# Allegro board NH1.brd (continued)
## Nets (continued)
+V_IPSOUT: C1AP1.1 C1AP4.1 C1AP5.1 C1AP8.1 C1AP12.1 C1AP14.1 C1AP20.1 C1AP31.1 C1AP34.1 C1AP37.1 C1AP42.1 C415.2 R1AP1.2 R1AP6.1 R56.2 R57.2 RT1HDMI1.1 U1AP1.8 U1AP1.15 U1AP1.19 U1AP1.22 U1AP1.25 U1AP1.26 U1AP1.37 U1AP1.43 U1AP1.44 U1AP1.45 U1AP1.59 U1AP1.60 U1AP1.72 U1AP1.76 U28.2 U28.3
+V_VBUS: C1AP15.1 C1P1.1 C1P2.1 CR1AP1.3 CR1P1.2 J1P1.1 R1AP6.2 R1AP7.2 U1AP1.55 U1AP1.61
+V_VCC: C1AP2.1 C1AP3.1 C1AP43.1 C1AP44.1 C1AS93.1 C1AS95.1 C1AS97.1 L1AP1.1 TVS2.2 U1.A12 U1.F15 U1.G15 U1.H14 U1.H15 U1.H16 U1.J17 U1.K13 U1.K14 U1.K15 U1.K16 U1.L14 U1.L15 U1.L16 U1.M14 U1.M15 U1.N14 U1.N15 U1.P13 U1.P14 U1.P15 U1.P16 U1AP1.29
+V_VCC_LX: L1AP1.2 U1AP1.27 U1AP1.28
+V_VNN: C1AP10.1 C1AP11.1 C1AP45.1 C1AS94.1 C1AS96.1 L1AP5.2 L1AP6.2 TVS1.2 U1.AB1 U1.K12 U1.L9 U1.L11 U1.L12 U1.L13 U1.M8 U1.M9 U1.M10 U1.M11 U1.M12 U1.N10 U1.N11 U1.N12 U1.R8 U1.R13 U1.T11 U1.T12 U1.T13 U1.T14 U1.T15 U1.T16 U1.T17 U1.U10 U1.U11 U1.U12 U1.U13 U1.U14 U1.U15 U1.U16 U1.V10 U1.V11 U1.V13 U1.V17 U1.V18 U1.W18 U1AP1.46
+V_VNN_PH1_LX: L1AP5.1 U1AP1.41 U1AP1.42
+V_VNN_PH2_LX: L1AP6.1 U1AP1.47 U1AP1.48
+V_VTT: C1AM25.1 C1AP36.1 R1AM13.1 R1AM20.1 R1AM21.1 U1AP1.7
+VREFCAL: C1AM5.2 C1AM11.2 R1AM5.1 R1AM6.2 U1AM1.M8 U1AM2.M8
+VREFCAU: C1AM17.2 C1AM23.2 R1AM9.1 R1AM10.2 U1AM3.M8 U1AM4.M8
+VREFDQL: C1AM6.2 C1AM12.2 R1AM7.1 R1AM8.2 U1AM1.H1 U1AM2.H1
+VREFDQU: C1AM18.2 C1AM24.2 R1AM11.1 R1AM12.2 U1AM3.H1 U1AM4.H1
+VRTC: C1AP35.1 CR1RTC1.1 U1AP1.53
+VRTC_CH: C1RTC1.1 CR1RTC1.3 R1AS5.1 R1AS11.1 U1.F11
+VSDIO: C1AS116.1 C88.2 R1AP11.2 U1.W14 U15.15 U15.16
+VSDIO1: R1AP12.1 R1WF13.2
ALDO1: C1AP21.1 U1AP1.33
ALDO2: C1AP22.1 U1AP1.34
ALDO3: C1AP23.1 U1AP1.36
BRTCX1_PAD_B8: C1AS66.1 R1AS54.1 U1.D1 Y1.2
BRTCX2_PAD_C7: C1AS67.1 R1AS54.2 U1.E1 Y1.1
BT_DEV_EN: R1WF3.1 U1.E16 U1WF1.12
BT_DEV_WAKE: R1WF5.1 U1.E17 U1WF1.20
BT_HOST_WAKE: U1.D9 U1WF1.21
BVCCRTC_EXPAD: C1AS65.1 U1.D2
CEXT_ALS: C1HDMI11.2 EU1HDMI1.17
COREPWROK: TP25.1 U1.F2 U1AP1.50
DDI0_HDMI_CLK_DN: C1HDMI2.1 EU1HDMI1.10
DDI0_HDMI_CLK_DN_ALS: J1HDMI1.12 L1HDMI1.2 R1HDMI10.2
DDI0_HDMI_CLK_DN_CH: EU1HDMI1.18 L1HDMI1.1 R1HDMI10.1
DDI0_HDMI_CLK_DP: C1HDMI1.1 EU1HDMI1.9
DDI0_HDMI_CLK_DP_ALS: J1HDMI1.10 L1HDMI1.3 R1HDMI9.2
DDI0_HDMI_CLK_DP_CH: EU1HDMI1.19 L1HDMI1.4 R1HDMI9.1
DDI0_HDMI_D0_DN: C1HDMI4.1 EU1HDMI1.7
DDI0_HDMI_D0_DN_ALS: EU1HDMI1.21 J1HDMI1.9
DDI0_HDMI_D0_DP: C1HDMI3.1 EU1HDMI1.6
DDI0_HDMI_D0_DP_ALS: EU1HDMI1.22 J1HDMI1.7
DDI0_HDMI_D1_DN: C1HDMI6.1 EU1HDMI1.5
DDI0_HDMI_D1_DN_ALS: EU1HDMI1.23 J1HDMI1.6
DDI0_HDMI_D1_DP: C1HDMI5.1 EU1HDMI1.4
DDI0_HDMI_D1_DP_ALS: EU1HDMI1.24 J1HDMI1.4
DDI0_HDMI_D2_DN: C1HDMI8.1 EU1HDMI1.2
DDI0_HDMI_D2_DN_ALS: EU1HDMI1.26 J1HDMI1.3
DDI0_HDMI_D2_DP: C1HDMI7.1 EU1HDMI1.1
DDI0_HDMI_D2_DP_ALS: EU1HDMI1.27 J1HDMI1.1
DDI0_HDMI_HPD_ALS: EU1HDMI1.25 J1HDMI1.19
DDI0_HDMI_HPD_ESD: EU1HDMI1.3 Q1HDMI2.1 R1HDMI6.2
DDI0_HDMI_SCL: EU1HDMI1.31 R1HDMI4.1 U1.C13
DDI0_HDMI_SCL_ALS: EU1HDMI1.28 J1HDMI1.15 R57.1
DDI0_HDMI_SDA: EU1HDMI1.32 R1HDMI5.1 U1.D13
DDI0_HDMI_SDA_ALS: EU1HDMI1.29 J1HDMI1.16 R56.1
DDI0_HPD_N: Q1HDMI2.3 R1HDMI3.1 U1.E14
DDI0_PLLOBS_DN: R1AS26.1 U1.AA4
DDI0_PLLOBS_DP: R1AS26.2 U1.AA3
DDI0_TX0_DN: C1HDMI8.2 U1.AB3
DDI0_TX0_DP: C1HDMI7.2 U1.AB4
DDI0_TX1_DN: C1HDMI6.2 U1.AA1
DDI0_TX1_DP: C1HDMI5.2 U1.AB2
DDI0_TX2_DN: C1HDMI4.2 U1.Y1
DDI0_TX2_DP: C1HDMI3.2 U1.Y2
DDI0_TX3_DN: C1HDMI2.2 U1.Y3
DDI0_TX3_DP: C1HDMI1.2 U1.Y4
DDR3_DRAM_PWROK: R1AS12.2 U1.AC20 U1AP1.11
DDR3_SOC_CMDPU: R1AS64.2 U1.AE21
DDR3_SOC_DQTPU: R1AS73.2 U1.AE20
DDR3_SOC_ODTPU: R1AS63.2 U1.AE22
DDR3_VCCA_PWROK: R1AS36.2 U1.AB20 U1AP1.12
DDR3_VREF: C1AS71.2 R1AS76.2 R1AS77.1 U1.AD20
DDR3L_ZQ_L8_A: R1AM1.1 U1AM1.L8
DDR3L_ZQ_L8_B: R1AM2.1 U1AM2.L8
DDR3L_ZQ_L8_C: R1AM3.1 U1AM3.L8
DDR3L_ZQ_L8_D: R1AM4.1 U1AM4.L8
DLD01: C1AP24.1 U1AP1.21
DLDO4: C1AP27.1 U1AP1.17
ELDO2: C1AP29.1 U1AP1.2
EMMC_CLK: U1.AE8 U1EMMC1.M6
EMMC_CMD: U1.AB8 U1EMMC1.M5
EMMC_DATA_0: U1.AB7 U1EMMC1.A3
EMMC_DATA_1: U1.AC7 U1EMMC1.A4
EMMC_DATA_2: U1.AC8 U1EMMC1.A5
EMMC_DATA_3: U1.AB9 U1EMMC1.B2
EMMC_DATA_4: U1.AA9 U1EMMC1.B3
EMMC_DATA_5: U1.AA8 U1EMMC1.B4
EMMC_DATA_6: U1.Y8 U1EMMC1.B5
EMMC_DATA_7: U1.Y7 U1EMMC1.B6
EMMC_RESET: U1.AD8 U1EMMC1.K5
GPIO_RCOMP: R1AS49.1 U1.A4
HDA_RCOMP: R1AS45.1 U1.AE14
HDMI_POWER_DN: EU1HDMI1.12 R1HDMI1.2
HOLD_N_FLASH: EU1SPI1.7 R1SPI4.1
I2C_4_PMIC_SCL: R69.2 TP24.1 U1.AE16 U1AP1.51
I2C_4_PMIC_SDA: R68.2 TP23.1 U1.AD16 U1AP1.52
I2S_1_BT_WWAN_CLK: U1.AC13 U1WF1.16
I2S_1_BT_WWAN_FS: U1.AC14 U1WF1.17
I2S_1_BT_WWAN_RXD: U1.Y10 U1WF1.14
I2S_1_BT_WWAN_TXD: U1.AB14 U1WF1.15
ICLK_ICOMP: R1AS51.1 U1.V1
M0_BS0: U1.M21 U1AM1.M2 U1AM2.M2 U1AM3.M2 U1AM4.M2
M0_BS1: U1.N19 U1AM1.N8 U1AM2.N8 U1AM3.N8 U1AM4.N8
M0_BS2: U1.K22 U1AM1.M3 U1AM2.M3 U1AM3.M3 U1AM4.M3
M0_CASB: U1.P20 U1AM1.K3 U1AM2.K3 U1AM3.K3 U1AM4.K3
M0_CKE0: R1AM13.2 U1.G22 U1AM1.K9 U1AM2.K9 U1AM3.K9 U1AM4.K9
M0_CLK0_DN: R1AS55.1 U1.J22 U1AM1.K7 U1AM2.K7 U1AM3.K7 U1AM4.K7
M0_CLK0_DP: R1AS55.2 U1.J23 U1AM1.J7 U1AM2.J7 U1AM3.J7 U1AM4.J7
M0_CS0_B: R1AM20.2 U1.P22 U1AM1.L2 U1AM2.L2 U1AM3.L2 U1AM4.L2
M0_DATA0: U1.D18 U1AM2.C8
M0_DATA1: U1.B18 U1AM2.A7
M0_DATA2: U1.A21 U1AM2.A3
M0_DATA3: U1.C18 U1AM2.B8
M0_DATA4: U1.A22 U1AM2.C2
M0_DATA5: U1.B20 U1AM2.D7
M0_DATA6: U1.A18 U1AM2.A2
M0_DATA7: U1.B22 U1AM2.C3
M0_DATA8: U1.C20 U1AM2.H3
M0_DATA9: U1.D23 U1AM2.F7
M0_DATA10: U1.E19 U1AM2.F2
M0_DATA11: U1.E23 U1AM2.H8
M0_DATA12: U1.D22 U1AM2.H7
M0_DATA13: U1.E22 U1AM2.F8
M0_DATA14: U1.E20 U1AM2.G2
M0_DATA15: U1.D20 U1AM2.E3
M0_DATA16: U1.E25 U1AM1.A3
M0_DATA17: U1.A23 U1AM1.C8
M0_DATA18: U1.C23 U1AM1.A7
M0_DATA19: U1.F25 U1AM1.C2
M0_DATA20: U1.B24 U1AM1.D7
M0_DATA21: U1.D24 U1AM1.C3
M0_DATA22: U1.B23 U1AM1.B8
M0_DATA23: U1.F24 U1AM1.A2
M0_DATA24: U1.F20 U1AM1.H8
M0_DATA25: U1.F21 U1AM1.H7
M0_DATA26: U1.G20 U1AM1.F7
M0_DATA27: U1.H23 U1AM1.H3
M0_DATA28: U1.G21 U1AM1.F8
M0_DATA29: U1.J21 U1AM1.F2
M0_DATA30: U1.J20 U1AM1.G2
M0_DATA31: U1.H22 U1AM1.E3
M0_DATA32: U1.AD24 U1AM3.A3
M0_DATA33: U1.AB25 U1AM3.A7
M0_DATA34: U1.Y24 U1AM3.B8
M0_DATA35: U1.AE23 U1AM3.A2
M0_DATA36: U1.AA25 U1AM3.D7
M0_DATA37: U1.AC23 U1AM3.C3
M0_DATA38: U1.AD23 U1AM3.C2
M0_DATA39: U1.Y25 U1AM3.C8
M0_DATA40: U1.V23 U1AM4.D7
M0_DATA41: U1.T24 U1AM4.C3
M0_DATA42: U1.W22 U1AM4.C8
M0_DATA43: U1.W23 U1AM4.B8
M0_DATA44: U1.R23 U1AM4.A2
M0_DATA45: U1.R22 U1AM4.C2
M0_DATA46: U1.V22 U1AM4.A7
M0_DATA47: U1.T25 U1AM4.A3
M0_DATA48: U1.AB22 U1AM4.H7
M0_DATA49: U1.AC22 U1AM4.F8
M0_DATA50: U1.Y19 U1AM4.G2
M0_DATA51: U1.AD22 U1AM4.F7
M0_DATA52: U1.AA22 U1AM4.H8
M0_DATA53: U1.Y23 U1AM4.E3
M0_DATA54: U1.Y20 U1AM4.H3
M0_DATA55: U1.Y21 U1AM4.F2
M0_DATA56: U1.T22 U1AM3.F7
M0_DATA57: U1.T20 U1AM3.F8
M0_DATA58: U1.W20 U1AM3.F2
M0_DATA59: U1.V20 U1AM3.H8
M0_DATA60: U1.U21 U1AM3.H3
M0_DATA61: U1.W21 U1AM3.E3
M0_DATA62: U1.U20 U1AM3.G2
M0_DATA63: U1.T21 U1AM3.H7
M0_DM0: U1.A20 U1AM2.D3
M0_DM1: U1.D21 U1AM2.E7
M0_DM2: U1.D25 U1AM1.D3
M0_DM3: U1.F19 U1AM1.E7
M0_DM4: U1.AC24 U1AM3.D3
M0_DM5: U1.V24 U1AM4.D3
M0_DM6: U1.Y22 U1AM4.E7
M0_DM7: U1.T23 U1AM3.E7
M0_DQS0_DN: U1.C19 U1AM2.B7
M0_DQS0_DP: U1.D19 U1AM2.C7
M0_DQS1_DN: U1.C21 U1AM2.G3
M0_DQS1_DP: U1.C22 U1AM2.F3
M0_DQS2_DN: U1.C25 U1AM1.B7
M0_DQS2_DP: U1.C24 U1AM1.C7
M0_DQS3_DN: U1.H19 U1AM1.G3
M0_DQS3_DP: U1.H20 U1AM1.F3
M0_DQS4_DN: U1.AB24 U1AM3.B7
M0_DQS4_DP: U1.AC25 U1AM3.C7
M0_DQS5_DN: U1.U25 U1AM4.B7
M0_DQS5_DP: U1.V25 U1AM4.C7
M0_DQS6_DN: U1.AA23 U1AM4.G3
M0_DQS6_DP: U1.AB23 U1AM4.F3
M0_DQS7_DN: U1.U23 U1AM3.G3
M0_DQS7_DP: U1.U22 U1AM3.F3
M0_DRAMRSTB: U1.U19 U1AM1.T2 U1AM2.T2 U1AM3.T2 U1AM4.T2
M0_MA0: U1.M24 U1AM1.N3 U1AM2.N3 U1AM3.N3 U1AM4.N3
M0_MA1: U1.L23 U1AM1.P7 U1AM2.P7 U1AM3.P7 U1AM4.P7
M0_MA2: U1.N23 U1AM1.P3 U1AM2.P3 U1AM3.P3 U1AM4.P3
M0_MA3: U1.M20 U1AM1.N2 U1AM2.N2 U1AM3.N2 U1AM4.N2
M0_MA4: U1.M22 U1AM1.P8 U1AM2.P8 U1AM3.P8 U1AM4.P8
M0_MA5: U1.L22 U1AM1.P2 U1AM2.P2 U1AM3.P2 U1AM4.P2
M0_MA6: U1.K24 U1AM1.R8 U1AM2.R8 U1AM3.R8 U1AM4.R8
M0_MA7: U1.N25 U1AM1.R2 U1AM2.R2 U1AM3.R2 U1AM4.R2
M0_MA8: U1.J25 U1AM1.T8 U1AM2.T8 U1AM3.T8 U1AM4.T8
M0_MA9: U1.H24 U1AM1.R3 U1AM2.R3 U1AM3.R3 U1AM4.R3
M0_MA10: U1.N20 U1AM1.L7 U1AM2.L7 U1AM3.L7 U1AM4.L7
M0_MA11: U1.K25 U1AM1.R7 U1AM2.R7 U1AM3.R7 U1AM4.R7
M0_MA12: U1.M25 U1AM1.N7 U1AM2.N7 U1AM3.N7 U1AM4.N7
M0_MA13: U1.M23 U1AM1.T3 U1AM2.T3 U1AM3.T3 U1AM4.T3
M0_MA14: U1.H25 U1AM1.T7 U1AM2.T7 U1AM3.T7 U1AM4.T7
M0_ODT0: R1AM21.2 U1.P24 U1AM1.K1 U1AM2.K1 U1AM3.K1 U1AM4.K1
M0_RASB: U1.N22 U1AM1.J3 U1AM2.J3 U1AM3.J3 U1AM4.J3
M0_WEB: U1.P21 U1AM1.L3 U1AM2.L3 U1AM3.L3 U1AM4.L3
MDSI_COMP: R1AS41.2 U1.P1
MSCI_COMP: R1AS42.2 U1.K1
NC_VSDIO: C1AP28.1 R1AP11.1 U1AP1.39
P0_REXT: R1AS13.1 U1.C1
P1_REXT: R1AS10.1 U1.A8
PLTRST_N: U1.B6 U1AP1.65
PMIC_USB2_DN: L1USB3.2 U1AP1.32
PMIC_USB2_DN_C: J1P1.2 L1USB3.1
PMIC_USB2_DP: L1USB3.3 U1AP1.31
PMIC_USB2_DP_C: J1P1.3 L1USB3.4
PMU_AC_PRESENT: R1AS1.2 U1.B8
PMU_BATLOW_N: R1AS2.2 U1.C9
PMU_PWRBTN_N: CR1P2.3 R1P1.1 U1.A10
PMU_SLP_S0IX_N: TP29.1 U1.C7 U1AP1.56
PMU_SLP_S3_N: Q1HDMI3.2 U1.C8
PWRON: C1P3.1 CR1P2.2 R1P2.2 U1AP1.62
REXT_ALS: EU1HDMI1.16 R1HDMI2.2
RSMRST_N: R1AP3.1 U1.F3 U1AP1.75
RTEST_N: C1AS5.1 R1AS5.2 U1.E3
RTL8723BS_EN: R1WF10.1 U1.C5
RTL8723BS_EN_R: R1WF1.2 R1WF10.2 R65.1 U1WF1.13
SDMMC1_RCOMP: R1AS43.1 U1.AE6
SDMMC2_CLK: C1WF21.2 U1.AE9 U1WF1.33
SDMMC2_CMD: U1.AC9 U1WF1.28
SDMMC2_D_0: U1.AB11 U1WF1.32
SDMMC2_D_1: U1.AB10 U1WF1.31
SDMMC2_D_2: U1.AC10 U1WF1.30
SDMMC2_D_3: U1.AD10 U1WF1.29
SDMMC3_CD_N: C73.1 J1SD1.9 R60.2 U1.Y12
SDMMC3_CLK: U1.AC12 U15.6
SDMMC3_CLK_CONN: R66.1 U15.11
SDMMC3_CLK_CONN_R: C418.2 J1SD1.5 R66.2
SDMMC3_CMD: U1.AB12 U15.5
SDMMC3_CMD_CONN: J1SD1.3 U15.12
SDMMC3_D_0: U1.AC11 U15.7
SDMMC3_D_1: U1.AB13 U15.8
SDMMC3_D_2: U1.AA12 U15.3
SDMMC3_D_3: U1.AA13 U15.4
SDMMC3_DATA0_CONN: J1SD1.7 U15.10
SDMMC3_DATA1_CONN: J1SD1.8 U15.9
SDMMC3_DATA2_CONN: J1SD1.1 U15.14
SDMMC3_DATA3_CONN: J1SD1.2 U15.13
SDMMC3_RCOMP: R1AS44.1 U1.AE10
SLP_S3_3P3_N: Q1HDMI3.3 R1HDMI1.1 R1HDMI8.1
SOC_PMIC_INT: R2AS4.1 TP26.1 U1.E9 U1AP1.64
SPI_NOR_CLK: EU1SPI1.6 U1.F12
SPI_NOR_CS0_N: EU1SPI1.1 R1SPI1.1 U1.C12
SPI_NOR_MISO: R1SPI3.2 U1.E13
SPI_NOR_MISO_R: EU1SPI1.2 R1SPI3.1
SPI_NOR_MOSI: EU1SPI1.5 U1.E12
SRTCRST_N: C1AS4.1 R1AS11.2 U1.E4
SUS_CLK_WLAN: R1WF11.1 U1.A9
SUSPWRDNACK: R63.1 U1.D10
SUSPWRDNACK_R: R63.2 R64.2 U1AP1.63
TP_CFG_ALS: EU1HDMI1.20 TP17.1
TP_DDI0_HDMI_CEC: J1HDMI1.13 TP12.1
TP_DDI0_HDMI_UTILITY: J1HDMI1.14 TP13.1
TP_EQ_ALS: EU1HDMI1.13 TP16.1
TP_LED_BT: TP18.1 U1WF1.5
TP_LED_WLAN: TP19.1 U1WF1.6
TP_PRE_ALS: EU1HDMI1.15 TP14.1
TP_WIFI_CLK_REQ: TP20.1 U1WF1.25
UART3_RXD: TP22.1 U1.AD6
UART3_TXD: TP21.1 U1.AC6
UART_1_BT_CTS: U1.AB18 U1WF1.24
UART_1_BT_RTS: U1.AC18 U1WF1.26
UART_1_BT_RXD: U1.AB19 U1WF1.27
UART_1_BT_TXD: U1.AC19 U1WF1.19
UART_RTS_8723: R1WF11.2 U1WF1.18
USB2_P0_CMC_DN: CR1USB2.2 J1USB3.3 L1USB1.1 R1USB1.2
USB2_P0_CMC_DP: CR1USB1.2 J1USB3.2 L1USB1.4 R1USB2.2
USB2_P0_DN: L1USB1.2 R1USB1.1 U1.G3
USB2_P0_DP: L1USB1.3 R1USB2.1 U1.G4
USB2_P1_CMC_DN: CR2USB1.2 J1USB2.2 L1USB2.1 R2USB1.2
USB2_P1_CMC_DP: CR2USB2.2 J1USB2.3 L1USB2.4 R2USB2.2
USB2_P1_DN: L1USB2.2 R2USB1.1 U1.H3
USB2_P1_DP: L1USB2.3 R2USB2.1 U1.H4
USB_OC#: C414.2 R1WF14.1 U1.F13 U28.5
USB_RCOMP: R1AS46.2 U1.F1
USB_ULPI_0_CS: R1AS4.1 U1.AE5
V_1P8_VINT: C1AP38.1 R1AP4.1 U1AP1.54
V_PMIC_VREF: C1AP40.1 U1AP1.38
V_USB: C1USB1.1 C1USB3.1 C417.2 CR1USB3.1 CR1USB4.2 J1USB2.1 J1USB3.4 U28.7 U28.8
WINDOWS_ANDROID: R58.1 R59.2 U1.AC5
WL_DEV_EN: R1WF4.1 U1WF1.10
WLAN_HOST_WAKE: R1WF6.2 U1WF1.11
WP_N_FLASH: EU1SPI1.3 R1SPI2.1
XDP_H_TCK: R2AS5.2 U1.E5
XDP_H_TDI: R2AS7.1 U1.F4
XDP_H_TMS: R2AS6.1 U1.H6
XDP_H_TRST_N: R2AS8.2 U1.G6
XTAL25_IN: R1AS52.1 U1.V3
XTAL25_IN_R1: C1AS63.1 R1AS50.2 R1AS52.2 Y2.1
XTAL25_OUT: R1AS53.1 U1.V2
XTAL25_OUT_R2: C1AS64.1 R1AS50.1 R1AS53.2 Y2.3
N01645: ANT1001.1 C1WF7.2 FB1WF3.1
N16460136: R1AP5.1 U1AP1.67 U1AP1.68
N16460500: R1AP2.2 U1AP1.35
N16461220: C1AP26.1 R1AP12.2 U1AP1.18
N16805407: CR1P3.2 R1P3.1
N16805481: R1P2.1 SW1P1.1
N16806211: CN15.2 CR1RTC1.2
N16894521: C1WF8.2 FB1WF3.2 U1WF1.8
N16982617: J1USB2.4 R2USB3.2
N16989050: CR1AP1.1 R1AP5.2 R1AP7.1 R1AP8.2
N16994583: R1AP1.1 U1AP1.70
N16996868: C1AP41.1 R1AP9.1 R1AP10.1 U1AP1.5
N17078120: R60.1 U1.AA5
N17101135: R62.1 U28.4
N17133316: R67.2 U1.U17

Pads without a net: CN15 3 4; CR1AP1 2; CR1P2 1; EU1HDMI1 8; J1P1 4; NOREF 1; NOREF#2 1; NOREF#4 1; NOREF#6 1; NOREF#7 1; NOREF#8 1; U1 A2 A3 A5 A6 A13 A14 A25 AA6 AA10 AA14 AA16 AA17 AA19 AA20 AB5 AB6 AB15 AB16 AB17 AB21 AC1 AC2 AC3 AC4 AC15 AC16 AC17 AC21 AD1 AD2 AD3 AD4 AD12 AD14 AD18 AE1 AE3 AE4 AE12 AE13 AE17 AE18 AE25 B2 B3 B4 B10 B12 B14 B16 B25 C2 C3 C4 C6 C10 C11 C14 C15 C16 C17 D3 D4 D5 D6 D7 D8 D11 D12 D14 D15 D16 D17 E6 E8 E10 F5 F6 F7 F8 F9 F10 F14 F16 F17 F18 F22 F23 G23 H1 H2 H5 J1 J3 J4 J5 J6 K2 K3 K4 K5 K6 K20 K21 K23 L3 L4 M1 M2 M3 M4 M5 M6 N1 N3 N4 N5 N6 P2 P3 P4 P5 P6 P10 P11 P23 P25 R3 R4 T1 T2 T3 T4 T5 T6 U1 U3 U4 U5 U6 U7 V4 V5 W3 W4 W6 Y5 Y6 Y9 Y13 Y14 Y16 Y17 Y18; U1AM1 J1 J9 L1 L9 M7; U1AM2 J1 J9 L1 L9 M7; U1AM3 J1 J9 L1 L9 M7; U1AM4 J1 J9 L1 L9 M7; U1AP1 3 40 57 58 69; U1EMMC1 A1 A2 A6 A7 A8 A9 A10 A11 A12 A13 A14 B1 B7 B8 B9 B10 B11 B12 B13 B14 C1 C3 C5 C7 C8 C9 C10 C11 C12 C13 C14 D1 D2 D3 D4 D12 D13 D14 E1 E2 E3 E5 E8 E9 E10 E12 E13 E14 F1 F2 F3 F10 F12 F13 F14 G1 G2 G3 G10 G12 G13 G14 H1 H2 H3 H5 H12 H13 H14 J1 J2 J3 J5 J12 J13 J14 K1 K2 K3 K6 K7 K10 K12 K13 K14 L1 L2 L3 L12 L13 L14 M1 M2 M3 M7 M8 M9 M10 M11 M12 M13 M14 N1 N3 N6 N7 N8 N9 N10 N11 N12 N13 N14 P1 P2 P7 P8 P9 P10 P11 P12 P13 P14; U1WF1 3 36 37 38 39 40 42 43 44 45 46; U15 1 2; U28 6

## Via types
v1: diameter 0.406, hole 0.203, TOP to BOTTOM, 896 vias
v2: diameter 0.508, hole 0.254, TOP to BOTTOM, 55 vias
v3: diameter 0.61, hole 0.356, TOP to BOTTOM, 25 vias

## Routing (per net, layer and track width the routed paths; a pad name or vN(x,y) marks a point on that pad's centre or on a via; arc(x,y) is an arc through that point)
+V1P0A: length 19
  TOP w0.203: v1(8.39,29.09) 8.55,28.93 U1AP1.13
  TOP w0.254: U1.G18 v1(10.11,55.46) ; v1(10.11,55.46) U1.G17 ; v1(10.11,55.46) U1.H18 ; C1AS70.1 22.59,61.91 22.59,60.56 v1(22.58,60.55) 22.58,60.39 21.93,59.75 U1.AE24 ; v1(12.76,54.14) U1.M16 v1(13.42,54.14) ; v1(15.4,54.79) U1.R17 U1.R18 ; U1.J16 v1(11.43,54.8) U1.K17 v1(12.09,54.8) U1.L17 ; U1.U18 v1(16.07,56.12) ; v1(9.45,56.13) U1.G19 9.78,56.45 v1(10.1,56.13) ; U1.W10 v1(17.4,50.16) ; v1(12.76,56.11) U1.M18 13.16,55.72 13.68,55.72 U1.N18
  TOP w0.381: v1(22.95,54.84) 23.76,54.01 C1AS200.1
  BOTTOM w0.381: v1(10.11,55.46) 10.11,56.13 ; 10.11,56.13 v1(10.1,56.13) ; 10.11,56.13 10.07,56.17 C1AS77.1 ; v1(17.4,50.16) 17.78,50.16 17.83,50.11 C1AS72.1
  BOTTOM w0.508: v1(5.05,55.48) 4.74,55.48 C1AS76.1
  vias: v1(4.86,49.26) v1(5.4,49.05) v1(6.01,27.39) v1(6.01,26.88) v1(6.01,26.37) v1(10.78,48.83) v1(11.43,49.5)
+V1P0SX: length 21.6
  TOP w0.203: U1AP1.73 11.35,33.8 11.49,33.66 v1(12.61,33.66)
  TOP w0.254: U1.H11 10.74,51.46 v1(10.78,51.46) 10.44,51.8 U1.H12 ; v1(15.41,48.13) 15.41,48.17 U1.T7 v1(16.07,48.83) ; 17.63,53.9 17.17,53.9 U1.V15 v1(16.73,54.14) U1.V16 17.63,53.9 ; 17.63,53.9 U1.W15 ; v1(15.41,51.48) U1.R11 15.41,50.82 ; v1(16.07,48.83) U1.T8 ; v1(16.07,48.83) U1.U8 ; 15.41,50.82 U1.R10 ; 15.41,50.82 U1.T10
  IN1 w0.381: v1(12.61,33.66) 11.52,34.75 11.52,37.95 11.29,38.18 v1(11.29,39.45)
  BOTTOM w0.381: 15.05,52.66 14.43,53.28 13.05,53.28 12.83,53.05 12.83,53.03 12.71,52.91 12.71,52.51 12.53,52.33 11.11,52.33 10.78,52 v1(10.78,51.46)
  vias: v1(11.81,39.45) v1(12.33,39.45) v1(12.84,39.45)
+V1P0SX_LX: length 0.9
  TOP w0.203: U1AP1.71 12.15,35.49
+V1P2A: length 4.8
  TOP w0.203: v1(7.88,32.34) 7.99,32.34 8.19,32.13 8.21,32.13 8.61,31.73 U1AP1.6
  TOP w0.305: U1.N7 13.42,48.18 v1(13.42,48.14) 13.09,48.48 U1.M7 ; U1.N7 13.75,48.47 v1(14.08,48.14) 14.41,48.47 U1.P7 ; U1.N7 U1.N8
  BOTTOM w0.203: v1(7.88,32.34) 7.92,32.37 C1AP33.1
+V1P2SX: length 16.1
  TOP w0.203: 7.86,33.69 8.36,33.18 8.36,32.92 8.76,32.53 U1AP1.4
  TOP w0.229: v1(10.77,52.81) U1.H13
  TOP w0.254: v1(9.43,52.79) U1.G13 9.88,52.58 10.33,52.58 U1.H13 ; U1.P9 14.41,49.84 14.09,50.16 v1(14.08,50.16) ; v1(14.75,56.12) U1.P19 ; v1(14.75,51.48) U1.P12
  TOP w0.381: v1(4.33,41.08) 3.85,41.08 TVS4.2 C1AP32.1 3.75,39.9 5.17,38.49 5.17,37.39 6.06,36.5 6.06,36.16 7.84,34.37 7.84,33.93 7.86,33.91 7.86,33.69
  BOTTOM w0.381: C1AS90.1 8.43,52.79 v1(9.43,52.79)
+V1P8A: length 74.6
  TOP w0.203: U1AP1.1 9.06,33.73 8.88,33.91 8.88,34.78 ; v1(27.85,66.22) 28.24,65.83 28.24,65.62 R58.2 ; R68.1 28.2,38.08 29.02,38.89 29.02,39.63 29,39.65
  TOP w0.229: U1.J15 v1(11.43,54.14) ; U1.W13 v1(17.4,52.15) U1.W12
  TOP w0.254: U1.G11 v1(10.11,50.82) U1.H10 10.77,50.82 U1.J10 U1.K10 ; v1(18.1,53.47) 18.42,53.8 U1.Y15 17.76,54.47 U1.W16
  TOP w0.305: 8.88,34.78 8.34,35.31 8.34,35.49 v1(7.91,35.92)
  TOP w0.381: 2.7,52.68 R1HDMI4.2 R1HDMI5.2 ; 30.39,40.18 30.85,39.72 v2(30.85,39.45) ; 30.39,40.18 29.86,39.65 29,39.65 28.3,40.35 27.63,40.35 27.41,40.57 R1SPI1.2 ; 30.39,40.18 R1SPI2.2 ; R1AS2.1 R1AS1.1 ; R69.1 R68.1 ; R1SPI4.2 27.59,49.93 v1(27.92,49.6) 28.29,49.6 28.57,49.88 EU1SPI1.8 ; v2(25.49,59.64) 25.49,59.55 C1EMMC5.2
  TOP w0.457: R1AS1.1 3,49.71 2.52,49.71 2.5,49.69 2.48,49.69 2.17,49.38 2.17,49.36 2.14,49.33 2.14,48.12 2.54,47.73 3.92,47.73 4.79,46.87 v1(5.29,46.87) ; R1AS2.1 2.49,51.24 2.49,52.47 2.7,52.68
  TOP w0.508: v1(7.91,35.92) 7.66,36.17 C1AP16.1 ; v2(30.85,20.22) 30.63,20.01 R1WF14.2
  IN1 w0.381: v2(30.85,20.22) 31.1,20.48 31.1,28.73 30.13,29.7 30.13,38.44 30.85,39.15 v2(30.85,39.45)
  BOTTOM w0.203: U1EMMC1.P5 U1EMMC1.N4 ; U1EMMC1.N4 U1EMMC1.M4 ; U1EMMC1.N4 U1EMMC1.P3 ; R1HDMI3.2 24.87,83.28 25.42,82.73 v1(25.56,82.73)
  BOTTOM w0.254: U1EMMC1.C6 26.12,53.91 v2(26.35,54.14) ; U1EMMC1.P5 25.62,59.51 v2(25.49,59.64)
  BOTTOM w0.381: Q1HDMI3.1 25.78,44.53 TVS5.2 ; Q1HDMI3.1 27.04,43.63 27.64,43.02 27.68,43.02 28.05,42.65 28.05,41.35 28.49,40.91 29.42,40.91 29.59,40.74 29.59,40.61 R1P1.2 30.75,39.45 v2(30.85,39.45) ; Q1HDMI3.1 27.96,45.46 27.96,49.56 v1(27.92,49.6) ; C1SPI1.2 27.75,66.32 v1(27.85,66.22)
  vias: v1(27.34,82.1)
+V3P3A: length 100.9
  TOP w0.203: U1AP1.24 11.75,26.19 11.64,26.29 v1(11.64,26.5)
  TOP w0.305: v1(9.43,51.46) U1.G12 ; U1.H9 v1(10.11,50.16)
  TOP w0.33: v1(27.62,56.64) 27.89,56.37 28.02,56.37 28.46,55.94 C1EMMC4.2
  TOP w0.381: C1EMMC4.2 29.28,56.42 29.19,56.51 C1EMMC1.2 30.18,58.05 30.18,59.48 29.61,60.05 28.7,60.05 v1(28.49,60.25)
  IN1 w0.254: v2(26.07,26.14) 22.36,22.43 18.2,22.43 16.37,24.26 16.06,24.26 14.87,25.46 11.97,25.46 11.95,25.48
  IN1 w0.381: v1(22.18,52.46) 21.93,52.71 18.66,52.71 18.29,52.34 17.9,52.34 17.56,52.67
  IN1 w0.457: v1(8.54,20.17) 9.43,20.17 11.64,22.38 11.64,25.65
  IN2 w0.457: v1(29.63,72.78) 30.44,73.59 30.44,75.9 30.03,76.31 30.03,82.06 30.45,82.48 30.48,82.48 31.15,83.15 31.15,87.8 31.29,87.94 v1(31.29,89.97)
  BOTTOM w0.203: C1AS99.1 10.07,52.09 v1(9.43,51.46) ; R1HDMI8.2 30.42,90.02 30.58,90.18 31.08,90.18 v1(31.29,89.97)
  BOTTOM w0.254: R62.2 25.69,25.76 v2(26.07,26.14) ; U1EMMC1.E6 26.12,55.14 ; 26.12,55.14 v1(27.62,56.64) ; 26.12,55.14 U1EMMC1.F5 ; v1(27.62,56.64) U1EMMC1.K9 ; v1(27.62,56.64) U1EMMC1.J10
  BOTTOM w0.457: v1(29.63,72.78) 29.29,72.44 29.29,67.52 29.77,67.05 29.77,64.76 29.25,64.24 29.25,61.47 28.49,60.72 v1(28.49,60.25) 29.08,59.67 30.48,59.67 30.77,59.38 30.77,52.43 29.06,50.72 26.61,50.72 25.89,49.99 24.92,49.99 23.39,51.52 22.61,51.52 22.18,51.95 v1(22.18,52.46)
  vias: v1(6.74,24.72) v1(7.25,24.72) v1(8.8,18.14) v1(9.43,18.14) v1(13.32,9.48) v1(13.32,8.97) v1(13.83,8.97) v1(15.15,4.17) v1(15.15,3.66) v3(9.46,38.61) v3(9.48,34.3)
+V3P3A_LX: length 1.2
  TOP w0.203: U1AP1.23 11.35,24.44
+V3P3A_SD: length 20.4
  TOP w0.203: U1AP1.20 10.15,25.26 9.99,25.09 8.92,25.09
  TOP w0.381: v1(6.46,18.32) 7.25,19.11 C1SD2.1 6.74,20.81 6.74,21.48 C1SD1.1 C1AP25.1 6.9,22.84 7.07,22.84 8.23,24 8.23,24.41 8.92,25.09 ; v1(5.29,12.48) 5.2,12.48 4.64,13.04 J1SD1.4
  IN1 w0.381: v1(5.29,12.48) 5.29,17.01 6.46,18.17 v1(6.46,18.32)
+V3P3S_WIFI: length 11.5
  TOP w0.381: R1WF12.2 4.01,23.06 v1(4.43,22.64) 4.01,22.21 R65.2
  IN2 w0.381: v1(6,24.74) v1(5.47,24.74) 5.47,24.08 4.43,23.04 v1(4.43,22.64)
  BOTTOM w0.381: v1(16.62,22.64) 17.23,22.64 17.87,23.27 C1WF9.2 19,23.18 C1WF10.2 18.73,21.79 17.6,21.79 16.96,21.15 U1WF1.35
+VDDI_EMMC: length 7.4
  TOP w0.381: v1(22.95,53.73) 23.12,53.75 23.32,53.55 23.32,53.54 23.87,52.99 C1EMMC2.2
  BOTTOM w0.076: U1EMMC1.C2 24.12,53.77 23.87,54.02 23.87,54.24 23.72,54.39 23.37,54.39 ; U1EMMC1.C2 23.87,53.39 23.3,53.39 ; U1EMMC1.C2 23.97,53.64 ; U1EMMC1.C2 23.97,53.64 ; 23.97,53.64 23.87,53.74 23.87,53.74 23.72,53.89 23.08,53.89
  BOTTOM w0.089: v1(22.95,53.73) 23.08,53.89 ; v1(22.95,53.73) 22.95,53.96 23.37,54.39 ; v1(22.95,53.73) 23.3,53.39
+VDDIO_WIFI: length 26.6
  TOP w0.381: v2(3.72,2.32) 3.08,2.95 R1WF4.2 ; v1(2.25,22.89) 3,22.89 R1WF12.1 R1WF3.2 ; R1WF5.2 R1WF1.1 2.53,22 v1(2.14,22.38)
  IN2 w0.381: v1(2.14,22.38) 2.14,3.89 v2(3.72,2.32)
  vias: v1(2.04,25.48) v1(2.04,24.97)
+VDDQ: length 20
  TOP w0.203: U1AM3.H2 24.93,74.34 24.93,75.14 v1(24.95,75.16) ; v2(26.62,63.62) C1AM21.2 C1AM10.2
  TOP w0.254: U1.L19 12.56,56.59 12.95,56.59 U1.M19 ; U1.L19 v1(12.09,56.12) ; U1.L19 v1(12.1,56.8) U1.L20 ; C1AM16.2 v2(27.51,76.06) ; U1.T19 v1(15.41,56.77) ; v1(12.09,56.12) U1.L18 ; v1(12.09,56.12) U1.K18 ; v1(4.11,78.36) U1AM1.N9 ; U1AM1.K8 v1(4.11,75.16) ; v2(27.27,59.95) 27.25,59.92 R1AS77.2 ; v1(9.68,67.74) 10.11,68.36 ; U1AM1.R9 v1(4.11,79.96) ; U1.W19 v1(17.4,56.77) ; 10.11,69.96 v1(10.67,69.96) ; v1(24.95,75.16) U1AM3.K2
  TOP w0.279: U1AM3.N9 18.41,77.96 v1(18.41,77.96)
  TOP w0.381: U1AM1.R1 v1(9.71,79.96) ; U1AM3.R9 v1(19.35,79.96)
  BOTTOM w0.089: 15.73,55.78 15.73,56.45 v1(15.41,56.77) 14.79,56.77 14.41,56.39 14.41,55.81
  BOTTOM w0.203: v1(9.68,67.74) 9.31,68.12 U1AM2.A8 ; U1AM4.A8 24.55,68.08
  BOTTOM w0.254: v1(4.11,78.36) U1AM1.N9 ; 24.55,68.08 v1(24.94,67.68) ; U1AM1.R9 v1(4.11,79.96) ; U1AM3.N1 v1(24.95,78.36)
  vias: v1(2.91,57.71) v1(2.91,57.21) v1(2.91,56.7) v1(3.31,79.96) v1(3.31,78.36) v1(4.09,67.58) v1(4.11,70.36) v1(4.99,30.15) v1(4.99,29.65) v1(4.99,29.14) v1(5.82,70.3) v1(6.1,81.45) v1(6.16,78.74) v1(7.07,72.22) v1(7.17,83.42) v1(7.34,76.31) v1(8.05,83.94) v1(9.68,83.27) v1(10.63,76.96) v1(11.23,78.83) v1(11.28,77.83) v1(11.43,57.47) v1(12.1,58.12) v1(12.43,84.66) v1(12.51,78.03) v1(12.87,69.43) v1(12.94,81.97) v1(13.12,71.94) v1(14.67,61.12) v1(14.84,77.5) v1(15.35,81.69) v1(16.37,77.74) v1(16.4,69) v1(16.57,83.44) v1(18.21,75.69) v1(18.4,70.76) v1(18.91,82.38) v1(19.33,70.38) v1(19.37,67.71) v1(20.45,84.85) v1(22.01,83.42) v1(22.08,76.31) v1(22.18,72.19) v1(22.24,67.75) v1(23.23,78.54) v1(23.29,72.99) v1(23.38,81) v1(24.94,79.96) v1(25.75,71.96) v1(25.75,71.16) v1(26.55,68.2)
GND: length 204.1
  TOP w0.102: U1.AA18 18.73,56.14 17.38,56.14 U1.V19 ; 9.76,50.48 U1.G10
  TOP w0.127: U1.E11 8.76,50.83 9.44,50.83
  TOP w0.203: U1.AA11 19.04,51.15 v1(18.73,51.47) ; U1.R19 14.92,56.61 14.92,56.99 U1.R20 15.08,57.15 15.23,57.29 15.23,57.65 U1.R21 ; U1.AD5 21.21,47.18 21.54,46.85 21.93,46.85 22.34,46.44 v1(22.34,46.16) ; v1(14.75,58.12) 14.56,58.12 14.56,58.12 14.29,58.12 14.28,58.12 14.07,58.12 U1.N21 ; U1AP1.30 14.15,25.06 14.39,24.82 ; U1AP1.49 17.61,30.53 17.33,30.26 v1(17.33,29.72)
  TOP w0.229: U1.J8 10.77,49.5 v1(10.78,49.48) ; U1.M13 U1.N13 ; U1.J14 v1(11.43,52.81) ; 12.09,50.82 U1.L10
  TOP w0.254: v1(4.91,75.16) 4.71,74.97 U1AM1.J8 ; U1AM3.B3 23.61,69.03 23.61,69.02 v1(23.35,68.76) ; U1AM3.D1 25.16,70.95 25.16,70.95 v1(24.95,71.16) ; U1.H21 v1(10.76,58.13) ; U1AM3.T9 v1(18.38,80.36) ; v1(24.95,71.16) 24.55,71.56 ; v1(24.95,71.16) 25.22,71.44 25.22,71.44 U1AM3.E1 ; U1AM1.M1 v1(10.51,77.56) ; v1(8.91,75.16) 9.31,74.76 U1AM1.J2 ; v1(4.11,72.76) 3.89,72.98 U1AM1.G9 ; v1(4.11,72.76) U1AM1.F9 ; v1(4.11,72.76) 4.31,72.97 4.31,72.97 U1AM1.G8 ; U1.U24 v1(16.73,60.07) ; U1.B21 v1(6.14,58.11) ; v1(9.71,71.16) 10.11,70.76 ; v1(9.71,71.16) U1AM1.E2 ; v1(9.71,71.16) U1AM1.E1 ; 4.51,70.76 v1(4.11,71.16) U1AM1.E8 ; v1(14.75,58.12) 14.95,57.93 U1.R21 ; U1AM1.G1 9.93,72.99 v1(9.71,72.76) ; v1(6,44.4) 6.15,44.56 U1.B1 ; U1.AD25 21.02,60.96 v1(21.08,61.02) ; U1.N24 v1(14.1,60.07) ; U1.E18 8.43,55.8 v1(8.74,56.11) ; U1AM3.A9 18.79,68.52 18.79,68.52 v1(18.55,68.76) 18.75,68.96 18.75,68.96 U1AM3.B9 ; U1AM3.G1 25.12,72.94 v1(24.95,72.76) ; U1.E2 v1(8.8,44.88) ; v1(17.13,88.02) 17.07,88.07 16.57,88.07 16.25,88.39 J1HDMI1.11 ; U1.AD13 20.7,52.15 v1(20.7,52.13) ; v1(14.08,56.12) U1.P18 v1(14.08,55.46) U1.P17 ; U1.E24 v1(8.8,60.07) ; v1(4.11,79.16) U1AM1.P9 ; U1.AA7 19.4,48.83 v1(19.4,48.84) ; U1.L8 v1(12.09,49.5) ; U1.AD9 v1(21.35,49.48) ; U1AM3.J2 24.31,75 24.31,75 v1(24.15,75.16) ; v1(15.42,52.15) 15.4,52.14 15.4,52.14 U1.R12 ; U1AM3.P9 v1(18.38,78.76) ; v1(9.43,54.82) 9.78,54.47 U1.G16 10.12,54.82 U1.H17 ; U1.AE2 v1(22.16,45.21) ; U1AM3.B1 25.35,69.16 v1(25.75,68.76) ; U1.R9 v1(15.41,50.16) ; U1AM1.M9 v1(4.11,77.56) ; U1.V14 v1(17.4,53.47) ; J1HDMI1.5 19.25,88.74 v1(18.55,88.04) ; v1(19.4,56.13) U1.AA18 ; U1AM3.F9 v1(19.39,72.77) ; v1(19.39,72.77) U1AM3.G8 ; v1(19.39,72.77) U1AM3.G9 ; v1(6.16,52.16) 6.16,52.16 U1.B13 ; v1(19.38,57.46) U1.AA21 ; v1(11.43,56.12) U1.J19 ; v1(11.43,56.12) U1.K19 ; v1(11.43,56.12) U1.J18 ; v1(10.7,78.59) 10.53,78.76 U1AM1.P1 ; v1(8.11,51.48) 8.43,51.16 U1.E11 ; v1(9.81,65.61) 9.81,66.24 C1AM8.1 ; v1(6.81,49.53) 6.48,49.8 U1.B9 ; U1.N17 v1(13.42,54.8) U1.M17 ; U1.R19 v1(15.41,56.12) U1.T18 ; C1AM19.1 16.51,66.63 v1(16.47,66.59) ; U1.L21 v1(12.75,57.47) ; U1.G10 9.44,50.83 ; v1(11.45,60.07) 11.43,60.07 U1.J24 ; 3.71,68.36 v1(3.31,68.76) 3.71,69.16 ; v1(24.29,62.97) 24.29,62.84 C1AS70.2 ; U1.V12 v1(16.73,52.15) ; 24.55,71.56 U1AM3.E2 24.55,71.56 ; U1.R15 15.08,53.8 v1(15.42,53.47) 15.07,53.14 U1.R14 ; v1(19.39,53.47) U1.AA15 ; U1AM3.D8 19.55,70.96 v1(19.35,71.16) U1AM3.E8 ; U1.W17 18.06,55.46 v1(18.1,55.46) ; C1AM16.1 v2(27.51,75.28) ; U1AM3.T1 v1(25.75,80.76) ; U1.E21 v1(8.13,58.1) ; v1(4.43,81.77) 3.75,82.44 C1AM4.1 ; U1.AA2 19.03,45.21 v1(18.7,44.88) ; v1(5.53,60.8) 5.42,60.7 5.42,60.12 U1.A24 ; U1AM3.P1 v1(24.95,79.16) ; C1AM17.1 v2(27.51,77.31) ; U1AM1.B1 10.11,69.16 v1(10.51,68.76) ; U1.AD17 v1(21.35,54.78) ; U1.AA24 v1(19.39,60.08) ; U1AM3.M9 v1(18.55,76.76) ; U1AM3.J8 19.93,74.58 v1(20.15,74.36) ; v1(20.7,57.46) 20.7,57.46 U1.AD21 ; U1.V21 v1(17.4,57.47) ; U1AM1.B3 8.33,68.99 8.33,68.99 v1(8.11,68.76) ; U1AM1.T1 10.4,80.66 10.5,80.66 v1(10.83,80.9) 10.83,81.26 10.46,81.63 C1AM14.1 C1AM7.1 ; U1AM1.T9 v1(4.11,80.76) ; J1HDMI1.17 13.25,88.68 12.84,88.27 12.61,88.27 12.51,88.17 v1(12.3,88.17) ; U1.B17 v1(6.16,55.45) ; C1AM24.1 v2(27.5,74.03) ; v1(24.95,77.56) U1AM3.M1 v1(24.95,77.56)
  TOP w0.305: v1(14.08,52.15) 13.75,52.48 U1.N13 ; v1(8.75,54.13) 8.43,53.82 U1.E15 ; R2USB3.1 7.31,33.44 7.02,33.15 7.02,33.15 6.53,32.66 C1AP36.2
  TOP w0.381: C1AM20.1 R1AM8.1 ; v1(20.97,37.94) 20.97,38.14 C1AS64.2 21.39,38.45 21.82,38.89 Y2.2 ; C1AS66.2 7.52,43.28 v1(7.78,43.54) ; v1(20.66,41.44) 20.84,41.26 C1AS63.2 ; v1(25.08,43.32) 25.08,44.01 R1AS4.2 ; R1AS10.2 3.07,48.97 v1(3.11,49) ; R1AS44.2 24.8,47.73 25.7,46.83 R1AS43.2 25.7,46.29 25.28,45.88 v1(24.95,46) ; v1(10.3,42.15) 10.33,42.19 C1AS67.2 ; v1(3.67,14.66) 3.11,14.66 2.53,15.24 J1SD1.6 ; C1AM10.1 C1AM21.1 25.85,64.23 v1(25.85,63.35) ; v1(25.26,41.48) 24.86,41.09 Y2.4 ; U1.G14 9.78,53.16 v1(9.46,53.47)
  TOP w0.508: PAD3.1 16.75,2.34
  VCC w0.089: 17.73,59.02 17.73,58.55 ; 17.05,59.09 17.05,58.45
  BOTTOM w0.076: 23.89,59.7 23.87,59.68 23.87,58.89 U1EMMC1.N2 24.37,58.89 24.37,59.71 24.37,59.72
  BOTTOM w0.203: 25.61,54.12 U1EMMC1.C4
  BOTTOM w0.254: R1AM3.2 16.03,78.16 16.18,78.16 16.19,78.17 16.54,78.17 16.55,78.16 16.57,78.16 17.56,77.17 18.14,77.17 v1(18.55,76.76) U1AM3.M9 ; v1(24.95,72.76) 25.17,72.98 25.17,72.98 U1AM3.G1 ; v1(24.95,72.76) 24.74,72.96 24.74,72.96 U1AM4.G8 ; v1(24.95,72.76) 25.15,72.56 U1AM4.F9 ; U1AM2.E1 3.89,71.38 v1(4.11,71.16) ; v1(16.75,44.88) 16.56,45.07 R1AS51.2 ; U1AM4.A9 v1(25.75,68.76) 25.35,69.16 U1AM3.B1 ; U1AM1.M1 10.25,77.3 v1(10.51,77.56) 10.73,77.56 11.39,76.9 R1AM2.2 ; U1AM2.A9 v1(10.51,68.76) 10.11,69.16 U1AM1.B1 ; U1AM3.T9 v1(18.38,80.36) ; v1(24.95,77.56) 25.16,77.35 25.16,77.35 U1AM3.M1 ; v1(19.39,53.47) 19.48,53.39 C1AS116.2 ; v1(20.15,74.36) 19.92,74.59 U1AM3.J8 ; R1AS41.1 14.26,45.07 v1(14.07,44.88) ; U1AM3.G9 v1(19.39,72.77) ; v1(19.35,71.16) U1AM3.E8 ; v1(19.35,71.16) 18.95,70.76 ; v1(19.35,71.16) U1AM4.E1 ; C1AS97.2 12.1,54.18 12.72,54.8 v1(13.42,54.8) ; U1AM3.J2 24.37,74.94 v1(24.15,75.16) ; C1AM1.1 18.34,83.07 v1(18.34,82.38) ; U1AM3.P1 v1(24.95,79.16) ; v1(10.7,78.59) 10.53,78.76 10.32,78.76 U1AM1.P1 ; U1AM4.B3 20.55,69.16 v1(20.95,68.76) ; C1HDMI9.2 14.64,86.21 13.52,87.33 12.58,87.33 12.3,87.61 v1(12.3,88.17) ; v1(26.91,67.37) 26.52,66.98 C1SPI1.1 26.52,66.18 27.22,65.48 R67.1 ; J1HDMI1.8 17.75,88.46 17.94,88.27 18.17,88.27 18.4,88.04 v1(18.55,88.04) ; C1AM16.1 v2(27.51,75.28) ; J1HDMI1.2 20.75,88.67 20.1,88.02 v1(20.03,88.02) ; U1AM3.P9 18.58,78.76 v1(18.38,78.76) ; v1(4.11,71.16) 3.9,70.95 3.78,70.83 U1AM2.D1 ; v1(4.11,71.16) 4.34,71.4 U1AM1.E8 ; U1AM1.E2 9.37,71.49 9.37,71.49 v1(9.71,71.16) 9.49,70.95 9.49,70.95 U1AM2.D8 ; U1AM2.G8 9.53,72.94 9.53,72.94 v1(9.71,72.76) ; v1(8.91,75.16) 9.14,74.93 9.24,74.83 9.24,74.83 U1AM1.J2 ; v1(10.83,80.9) 10.65,80.9 10.44,80.7 U1AM1.T1 ; U1WF1.9 v1(6.27,9.58) ; U1AM1.B9 3.71,69.16 v1(3.31,68.76) ; C1AM24.1 v2(27.5,74.03) ; v1(9.71,72.76) 9.91,72.56 U1AM2.F9 ; v1(9.71,72.76) 9.96,73.02 9.96,73.02 U1AM1.G1 ; v1(4.11,77.56) 3.91,77.37 U1AM1.M9 ; v1(8.37,9.58) U1WF1.7 ; U1AM1.P9 v1(4.11,79.16) ; v1(5.71,68.76) 5.37,69.09 5.37,69.09 U1AM2.B3 ; U1WF1.4 11.52,9.2 v1(11.14,9.58) ; U1AM4.D8 v1(24.95,71.16) 24.55,71.56 U1AM3.E2 ; v1(21.44,84.43) 21.52,84.43 21.53,84.42 C1AS84.2 ; C1AM17.1 v2(27.51,77.31) ; U1AM1.T9 v1(4.11,80.76) ; v1(18.55,68.76) 18.95,69.16 U1AM3.B9 ; U1AM1.G9 3.94,72.93 3.94,72.93 v1(4.11,72.76) ; U1AM3.T1 v1(25.75,80.76) ; U1AM1.J8 v1(4.91,75.16)
  BOTTOM w0.305: R1HDMI6.1 26.7,83.48 26.98,83.19 28.3,83.19 v1(28.51,82.99)
  BOTTOM w0.381: v1(10.83,80.9) 11.26,81.33 C1AM9.1 ; v1(16.4,69.89) 16.35,69.83 C1AM33.2 ; C1AS96.2 14,49.41 v1(14.08,49.5) 13.94,49.5 13.56,49.88 C1AS94.2 ; v1(9.46,53.47) 9.67,53.47 C1AS99.2 ; v1(16.73,52.15) 16.81,52.22 C1AS80.2 ; C1AS90.2 8.51,54.13 v1(8.75,54.13) ; v1(5.95,33.56) 5.75,33.56 4.59,34.72 CR2USB2.1 ; v1(3.11,49) 3.09,48.99 C1RTC1.2 ; C1AS72.2 18.22,50.89 18.73,51.41 v1(18.73,51.47) ; 11.69,36.61 9.42,36.61 8.13,35.32 CR2USB1.1 ; C1AM22.1 16.35,66.71 v1(16.47,66.59) ; C1AS86.2 1.6,71.49 2.07,71.02 v1(2.07,70.58) ; C1AM35.2 13.04,68.36 v1(12.87,68.54) 12.87,67.18 C1AM2.1 ; C1AS89.2 C1AS88.2 12.86,48.7 12.09,49.46 v1(12.09,49.5) ; C1AS95.2 13.93,51.48 v1(14.08,51.48) ; C1AS78.2 C1AS69.2 11.42,51.44 v1(11.43,51.46) ; v1(18.1,55.46) 18.57,54.99 C1AS201.2 ; C1AS81.2 C1AS79.2 17.06,48.5 v1(16.73,48.83) ; v2(27.52,70.35) 27.76,70.35 C1AS87.2 ; v1(6.82,48.15) 7.61,48.15 R2AS5.1 8.1,48.65 R2AS8.1
  BOTTOM w0.406: TVS5.1 25.33,45.63 v1(24.95,46) ; C1AP17.2 9.53,60.08 8.8,60.08 v1(8.8,60.07) ; C1AP18.2 9.94,58.67 9.94,57.9 C1AS77.2 10.32,57.77 10.67,58.13 v1(10.76,58.13) ; v1(12.75,57.47) 12.75,58.12 C1AP19.2
  BOTTOM w0.457: v2(2.19,55.15) 2.86,54.49 C1AS76.2 ; C1AM36.2 13.04,60.53 13.64,60.53 v1(14.1,60.07)
  BOTTOM w0.508: EU1HDMI1.34 28.56,84.71 Q1HDMI2.2 ; PAD3.1 16.75,2.31 ; CN15.1 11.9,46.65 v1(12.1,46.84)
  vias: v1(0.75,42.83) v1(0.77,29.49) v1(0.72,2.34) v1(0.72,1.2) v1(0.8,83.04) v1(0.8,80.5) v1(0.8,77.96) v1(0.8,75.42) v1(0.8,72.88) v1(0.8,70.34) v1(0.8,60.05) v1(0.8,57.51) v1(0.8,54.97) v1(0.8,52.43) v1(0.8,49.89) v1(0.8,47.35) v1(0.8,4.42) v1(0.8,3.66) v1(1.53,4.65) v1(1.94,29.44) v1(2.12,46.72) v1(2.19,44.53) v1(3.16,0.74) v1(3.46,91.04) v1(4.23,84.69) v1(4.38,25.33) v1(4.38,24.82) v1(4.76,51.14) v1(4.99,88.37) v1(5.14,85.07) v1(5.55,18.22) v1(5.75,88.47) v1(5.78,41.09) v1(5.78,40.58) v1(6.06,91.06) v1(6.16,27.97) v1(6.64,88.24) v1(7.27,38.38) v1(7.27,34.17) v1(7.91,91.04) v1(8.29,2.93) v1(8.29,2.16) v1(8.29,1.4) v1(8.29,0.72) v1(8.88,40.99) v1(9.1,0.77) v1(9.41,48.83) v1(9.46,46.21) v1(10.27,26.5) v1(10.42,0.79) v1(10.7,37.95) v1(10.71,19.29) v1(10.88,26.5) v1(11.39,28.53) v1(11.59,19.28) v1(11.64,0.77) v1(11.97,41.53) v1(12.74,46.84) v1(13.47,2.47) v1(13.47,1.71) v1(13.73,37.93) v1(13.83,26.55) v1(13.91,38.46) v1(14.57,23.15) v1(14.64,24.36) v1(14.98,24.75) v1(14.97,16.18) v1(15.71,26.5) v1(16.22,7.29) v1(16.76,38.82) v1(17.03,7.5) v1(17.03,6.89) v1(17.89,19.06) v1(17.87,13.8) v1(17.93,9.45) v1(18.19,20.83) v1(18.27,13.42) v1(18.63,21.11) v1(18.7,42.75) v1(20.08,43.57) v1(20.18,20.15) v1(20.53,21.26) v1(21.12,27.22) v1(21.75,33.51) v1(21.8,0.77) v1(22.26,33.51) v1(22.26,24.16) v1(22.46,65.54) v1(23.16,55.38) v1(24.34,0.77) v1(24.88,90.41) v1(25.09,54.72) v1(25.56,37.01) v1(25.51,35.54) v1(25.94,27.23) v1(25.94,26.7) v1(26.12,29.65) v1(26.12,29.09) v1(26.12,28.53) v1(26.78,24.01) v1(26.78,23.5) v1(26.82,62.74) v1(26.82,62.13) v1(26.82,61.63) v1(26.88,0.77) v1(27.29,23.45) v1(27.39,57.61) v1(27.52,18.58) v1(27.52,1.68) v1(27.65,90.45) v1(28.03,44.69) v1(28.39,91.04) v1(28.39,57.71) v1(28.51,81.01) v1(28.6,55.23) v1(28.6,54.72) v1(28.6,54.21) v1(29.05,35.96) v1(29.42,0.77) v1(29.63,17.76) v1(30.04,91.04) v1(31.2,69.58) v1(31.39,64.83) v1(31.51,79.48) v1(31.75,52.78) v1(31.76,23.96) v1(31.81,85.51) v1(32.01,80.35) v1(32.01,78.82) v1(32.04,17.76) v1(32.17,20.17) v1(32.17,19.28) v1(32.29,89.9) v1(32.62,88.37) v1(32.67,47.73) v1(32.67,45.57) v1(32.67,41.64) v1(32.67,39.35) v1(32.67,29.57) v1(32.67,21.7) v1(32.67,19.66) v1(32.73,52.71) v1(32.75,49.36) v1(32.7,28.99) v1(32.7,28.35) v2(1.38,3.64) v2(2.35,42.3) v2(5.5,31.37) v2(5.5,30.76) v2(26.67,59.7) v2(27.99,59.7) v3(13.57,29.19) v3(15.45,29.55) v3(15.76,32.09) v3(15.73,27.74)
VDDQSET: length 10.1
  TOP w0.102: U1AP1.66 14.15,33.68 v1(14.36,33.47) ; R1AP4.2 21.32,34.65 v1(21.7,34.27)
  IN1 w0.102: v1(14.36,33.47) 15.37,33.47 15.76,33.08 20.51,33.08 v1(21.7,34.27)
+V_HDMI_CONN: length 10.5
  BOTTOM w0.381: RT1HDMI1.2 9,86.39 9.17,86.22 9.27,86.22 9.52,85.98 TVS7.2 C1HDMI10.2 11.49,85.98 11.73,86.21 C1HDMI9.1 12.53,86.75 11.77,87.51 11.77,88.5 12.13,88.85 12.33,88.85 12.75,89.28 J1HDMI1.18
+V_IPSOUT: length 62.5
  TOP w0.203: U1AP1.15 8.5,28.13 v1(8.24,27.87) ; v1(10.37,32.24) 10.37,31.27 10.03,30.93 U1AP1.8 ; U1AP1.22 10.95,24.64 v1(10.93,24.62)
  TOP w0.381: v1(14.64,37.72) 14.24,37.33 R1AP1.2 ; v3(8.85,25.94) 8.85,25.71 8.79,25.71 8.79,25.65 7.74,24.61 7.74,24.49 7.11,23.86 C1AP20.1
  IN1 w0.457: v1(6.46,88.93) 7.48,88.93 8.98,87.43 10.75,87.43 13.35,90.02 21.73,90.02 22.42,89.33 22.42,87.77 22.69,87.51 25.57,87.51 26.82,88.75 26.82,88.76 28.15,90.1 30.25,90.1 v1(30.73,89.62)
  IN2 w0.457: 27.98,81.18 v1(27.95,81.16) ; 27.98,81.18 27.98,81.19 27.98,82.32 27.98,82.32 27.98,83.88 30.54,86.44 30.54,87.98 30.73,88.17 v1(30.73,89.62) ; 27.98,81.18 27.98,81.23 28.29,81.54 28.79,81.54 29.42,80.9 29.42,74.66 29.63,74.45 v1(29.63,74.15)
  BOTTOM w0.381: R57.2 30.6,71.91 30.6,73.48 30.01,74.08 29.64,74.08 v1(29.63,74.15) ; RT1HDMI1.1 7.45,89.29 7.1,88.93 v1(6.46,88.93)
  BOTTOM w0.457: v1(27.95,81.16) 27.95,82.38 27.65,82.68 R56.2
  vias: v1(19.24,38.71) v1(19.24,38.08) v1(19.24,36.56) v1(20,38.08) v2(9.43,35.67) v3(10.81,35.95) v3(12.61,26.6) v3(17.71,24.26) v3(18.43,24.09) v3(19.21,28.43) v3(21.45,21.67) v3(22.21,21.67)
+V_VBUS: length 6.2
  TOP w0.381: v3(16.16,36.35) 16.16,38.72 R1AP7.2 15.28,40.39 CR1AP1.3
  vias: v2(25.72,34.98) v2(25.72,34.27) v2(25.72,33.61) v3(16.15,35.59) v3(19.47,34.98) v3(19.92,35.59)
+V_VCC: length 15
  TOP w0.203: v1(14.11,24.52) 13.75,24.87 U1AP1.29
  TOP w0.305: v1(5.4,51.69) 5.72,51.69 U1.A12
  TOP w0.381: C1AS93.1 3.96,51.78 5.31,51.78 v1(5.4,51.69)
  IN1 w0.381: v1(14.11,24.52) 14.03,24.44 14.03,24.16 14.43,23.76 16.26,23.76 17.46,22.56 17.46,21.73 15.98,20.25 15.45,20.25 14.64,19.44 v3(14.23,19.44)
  BOTTOM w0.381: C1AS95.1 13.97,52.69 v1(14.08,52.81) ; v1(12.09,52.81) 12.1,52.82 C1AS97.1
  BOTTOM w0.406: v1(14.11,24.52) 14.11,24.76 TVS2.2
  vias: v1(10.77,53.47) v1(11.43,53.47) v1(14.08,54.14) v2(14.56,20.4) v3(13.95,20.1)
+V_VNN: length 10.3
  TOP w0.203: U1AP1.46 17.57,29.33 v1(17.31,29.06)
  TOP w0.254: U1.AB1 19.73,44.56 v1(20.03,44.18) ; U1.R8 v1(14.74,49.5)
  IN1 w0.381: v1(17.31,29.06) 22.03,29.06 v3(22.82,28.28)
  BOTTOM w0.203: TVS1.2 17.31,28.37 v1(17.31,29.06)
  BOTTOM w0.381: v1(14.08,50.81) 13.93,50.66 C1AS94.1 ; v1(14.74,49.5) 14.74,48.74 C1AS96.1
  vias: v1(12.76,49.51) v1(16.07,54.13) v1(16.07,51.48) v1(16.07,50.82) v1(16.07,50.16) v1(17.4,55.46) v3(22.21,27.26) v3(22.92,27.51) v3(23.02,26.14) v3(23.02,25.43)
+V_VTT: length 86.5
  TOP w0.203: 8.44,31.33 U1AP1.7
  IN2 w0.457: v1(8.34,85.53) 7.99,85.88 4.2,85.88 2.4,84.08 2.4,81.49 1.41,80.5 1.41,41.84 2.11,41.14 2.11,41.14 2.11,39.95 2.4,39.66 2.4,39.64 2.68,39.37 2.68,38.42 3.52,37.58 3.52,35.84 3.01,35.34 3.01,32.64 3.36,32.29 3.36,29.42 4.25,28.53
  IN2 w0.508: v1(7.53,31.88) 7.53,30.26 5.8,28.53 4.25,28.53
  BOTTOM w0.381: R1AM21.1 13.86,74.78 13.86,74.9 14.03,75.07 14.2,75.07 14.56,75.43 R1AM13.1 14.56,75.91 13.78,76.69 R1AM20.1 13.68,76.92 13.68,82.1 13.19,82.58 11.98,82.58 11.44,83.12 10.32,83.12 9.95,82.76 9.39,82.76 9.09,83.06 9.09,83.75 8.48,84.36 C1AM25.1
  vias: v1(8.95,85.78)
+VREFCAL: length 15.3
  TOP w0.203: v1(2.34,78.04) 2.02,77.71 C1AM11.2 R1AM6.2 ; U1AM1.M8 v1(4.12,76.78)
  IN2 w0.203: v1(9.71,76.76) 9.05,76.1 8.07,76.1 7.88,75.9 5,75.9 v1(4.12,76.78)
  BOTTOM w0.203: v1(4.12,76.78) 3.4,76.78 2.72,77.46 2.72,77.66 v1(2.34,78.04) 1.94,78.43 1.94,79.11 C1AM5.2 R1AM5.1 ; U1AM2.M8 9.48,76.99 9.48,76.99 9.71,76.76 v1(9.71,76.76)
+VREFCAU: length 14.2
  TOP w0.203: 25.74,76.76 v1(24.95,76.76) ; U1AM3.M8 v1(19.35,76.76)
  TOP w0.254: 25.74,76.76 25.8,76.76 v1(27.73,78.69) ; v1(27.73,78.69) 27.73,78.5 C1AM17.2 ; v1(27.73,78.69) 27.73,78.94 R1AM10.2
  IN2 w0.203: v1(19.35,76.76) 19.88,76.23 21.47,76.23 21.8,75.9 22.54,75.9 23.4,76.76 v1(24.95,76.76)
  BOTTOM w0.254: C1AM17.2 27.73,78.5 v1(27.73,78.69) 27.73,78.94 R1AM10.2
  BOTTOM w0.381: U1AM4.M8 v1(24.95,76.76)
+VREFDQL: length 19.3
  TOP w0.254: v1(11.11,74.71) 10.85,74.71 10.43,74.29 U1AM1.H1 ; 2.25,74.03 v1(2.94,74.73)
  TOP w0.381: 2.25,74.03 2.25,73.56 1.56,72.87 C1AM12.2 R1AM8.2
  IN1 w0.254: v1(2.94,74.73) 4.29,76.08 6.89,76.08 7.09,75.88 9.94,75.88 v1(11.11,74.71)
  BOTTOM w0.254: 3.11,73.36 U1AM2.H1 3.37,74.3 3.05,74.62 3.05,74.63 v1(2.94,74.73)
  BOTTOM w0.381: C1AM6.2 R1AM7.1 1.58,73.38 3.09,73.38 3.11,73.36
+VREFDQU: length 19.4
  TOP w0.254: U1AM3.H1 25.35,73.87 26.06,73.16 v1(26.11,73.16) 26.2,73.25 C1AM24.2 R1AM12.2
  IN1 w0.254: v1(18.35,74.66) 19.57,75.87 22.23,75.87 22.3,75.95 24.94,75.95 26.26,74.63 26.26,73.31 v1(26.11,73.16)
  BOTTOM w0.254: v1(18.35,74.66) 18.35,74.33 18.71,73.96 U1AM4.H1 ; v1(26.11,73.16) 26.2,73.25 C1AM24.2 R1AM12.2
+VRTC: length 52.4
  TOP w0.203: v1(19.36,32.19) 19.31,32.13 U1AP1.53
  TOP w0.381: C1AP35.1 19.67,32.49 v1(19.36,32.19)
  IN1 w0.381: v1(1.81,28.94) 2.19,28.94 3.35,30.09 3.35,37.94 v1(2.14,39.15)
  IN2 w0.381: v1(1.81,28.94) 2.26,28.94 5.85,25.34 17.01,25.34 19.81,28.14 19.81,28.74 19.36,29.18 v1(19.36,32.19)
  BOTTOM w0.381: v1(2.14,39.15) 2.09,41.08 1.31,41.86 1.31,51.36 CR1RTC1.1
+VRTC_CH: length 21
  TOP w0.254: U1.F11 v1(8.76,51.48)
  TOP w0.381: R1AS5.1 2.78,43.03 v1(2.5,43.31) 2.5,43.69 2.85,44.05 R1AS11.1
  IN1 w0.457: v1(8.76,51.48) 8.76,51.41 8.32,50.97 7.38,50.97 7.02,51.33 6.41,51.33 5.4,50.32 2.88,50.32 2.12,49.56 v1(2.12,47.22) 2.33,47.22 2.63,46.93 2.63,46.92 2.8,46.74 2.8,43.62 v1(2.5,43.31)
  BOTTOM w0.381: CR1RTC1.3 1.99,49.5 1.99,48.44 2.23,48.21 C1RTC1.1 2.55,47.66 v1(2.12,47.22)
+VSDIO: length 82.9
  TOP w0.305: U1.W14 18.06,52.81 v1(18.09,52.81)
  TOP w0.457: 15.4,10.5 15.15,10.24 ; v1(22.95,24.78) 23.14,24.59 27.06,24.59 27.34,24.31 v1(27.34,24.01)
  TOP w0.508: v1(10.32,10.76) 12.69,10.76 13.21,10.24 15.15,10.24 15.15,9.51 16.03,8.63 C88.2
  IN1 w0.508: v1(10.32,10.76) v1(10.32,15.73)
  IN2 w0.508: v1(10.32,15.73) 10.42,15.63 15.43,15.63 18.76,18.95 18.87,18.95 18.87,18.95 20.63,18.95 21.03,19.36 24.98,19.36 27.85,22.23 27.85,23.68 27.52,24.01 v1(27.34,24.01) 27.34,25.28 27.51,25.45 27.85,25.79 27.85,39.92 26.88,40.88 26.88,50.63 27.77,51.52 27.77,52.18 26.66,53.29 25.23,53.29 24.24,54.28 22.26,54.28 22.03,54.06 19.22,54.06 18.86,53.7 18.86,53.37 18.3,52.81 v1(18.09,52.81)
  BOTTOM w0.254: C1AS116.1 18.69,52.81 v1(18.09,52.81)
  BOTTOM w0.457: R1AP11.2 21.64,24.78 v1(22.95,24.78)
ALDO1: length 1.7
  TOP w0.102: U1AP1.33 15.35,24.19 C1AP21.1
ALDO2: length 1.8
  TOP w0.203: U1AP1.34 15.75,24.52
  TOP w0.356: 15.75,24.52 16.16,24.11 C1AP22.1
ALDO3: length 2.4
  TOP w0.102: U1AP1.36 16.55,24.99 16.65,24.89 16.65,24.01 17.03,23.62 C1AP23.1
BRTCX1_PAD_B8: length 5.1
  TOP w0.102: Y1.2 7.73,40.95 R1AS54.1 8.3,42 C1AS66.1 8.48,42.96 8.48,43.86 U1.D1
BRTCX2_PAD_C7: length 5.2
  TOP w0.102: Y1.1 10.23,40.85 R1AS54.2 9.55,42 C1AS67.1 9.27,43.06 9.27,43.74 U1.E1
BT_DEV_EN: length 65.4
  TOP w0.102: R1WF3.1 4.01,23.87 4.84,23.04 4.84,21.57 5.14,21.26 5.14,20.05 4.84,19.74 4.63,19.74 4.48,19.59 4.48,17.85 4.79,17.54 4.79,16.79 v1(4.63,16.64) ; v1(5.95,53.93) 6.37,53.93 6.78,54.33 6.78,54.52 7.08,54.82 8.07,54.82 U1.E16
  IN1 w0.102: v2(4.18,9.41) 4.18,9.43 4.67,9.92 4.67,14.94 4.19,15.42 4.19,16.2 v1(4.63,16.64) 4.63,16.74 4.4,16.97 3.7,16.97 2.75,17.91 2.75,21.98 2.96,22.18 2.96,23.34 2.75,23.55 2.75,28.53 4.05,29.83 4.05,38.66 2.8,39.91 2.8,40.76 1.58,41.98 1.58,50.17 2.88,51.47 4.96,51.47 5.12,51.31 5.65,51.31 5.8,51.47 5.8,53.78 v1(5.95,53.93)
  BOTTOM w0.102: U1WF1.12 3.11,8.26 4.21,9.36 v2(4.18,9.41)
BT_DEV_WAKE: length 47.4
  TOP w0.102: R1WF5.1 1.53,19.44 v1(1.59,19.39) ; v1(8.76,54.81) 8.75,54.81 U1.E17
  IN1 w0.102: v1(1.59,19.39) 2.4,20.2 2.4,22.13 2.6,22.33 2.6,23.2 2.4,23.4 2.4,28.68 3.67,29.95 3.67,38.44 2.45,39.65 2.45,40.54 1.15,41.84 1.15,50.75 2.64,52.25 4.93,52.25 4.94,52.25 5.19,52.51 5.19,53.99 5.92,54.72 8.67,54.72 v1(8.76,54.81)
  BOTTOM w0.102: U1WF1.20 2.02,17.63 1.84,17.81 1.84,19.13 v1(1.59,19.39)
BT_HOST_WAKE: length 41.2
  TOP w0.102: U1.D9 v1(7.46,50.18)
  IN1 w0.102: v1(7.46,50.18) 6.95,50.18 6.31,49.54 6.31,49 5.78,48.47 5.15,48.47 5,48.62 4.37,48.62 3.52,47.77 3.52,42.46 4.85,41.13 4.85,38.17 6.46,36.56 6.46,35.46 7.61,34.32 7.61,33.48 7.02,32.9 7.02,29.59 5.32,27.89 5.32,26.37 4.96,26.01 4.96,24.96 4.96,24.41 5.85,23.53 5.85,19.54 v1(5.55,19.23)
  BOTTOM w0.102: v1(5.55,19.23) 4.94,19.84 4.53,19.84 3.49,18.8 U1WF1.21
BVCCRTC_EXPAD: length 4.5
  TOP w0.137: 7.49,44.44 7.49,44.69
  TOP w0.152: U1.D2 7.78,44.99 7.49,44.69 ; C1AS65.1 6.44,42.98 7.49,44.03 7.49,44.44
CEXT_ALS: length 2.2
  TOP w0.102: v1(25,88.32) 25.11,88.21 EU1HDMI1.17
  BOTTOM w0.102: C1HDMI11.2 25.52,88.32 v1(25,88.32)
COREPWROK: length 21
  TOP w0.102: U1.F2 9.17,45.21 v1(9.5,44.88) ; v1(12.66,40.87) 13.22,41.43 TP25.1 ; U1AP1.50 17.32,30.93 v1(17.31,30.92)
  IN1 w0.102: v1(9.5,44.88) 9.49,44.88 9.49,44.37 9.87,44 10.44,44 10.96,43.48 10.96,41.64 11.72,40.87 v1(12.66,40.87)
  IN2 w0.102: v1(12.66,40.87) 12.66,40.17 13.37,39.46 13.37,37.47 14.36,36.48 15.12,36.48 15.66,35.95 15.66,35.01 17.31,33.36 v1(17.31,30.92)
DDI0_HDMI_CLK_DN: length 2.6
  TOP w0.131: EU1HDMI1.10 29.24,87.81 29.32,87.73 29.51,87.73 29.64,87.86 29.64,88.22 30.06,88.64 30.3,88.64 30.42,88.76 C1HDMI2.1
DDI0_HDMI_CLK_DN_ALS: length 14
  TOP w0.131: R1HDMI10.2 20.44,86.43 19.34,86.43 19.19,86.58 17.19,86.58 16.85,86.24 16.85,86.01 v1(16.6,85.76)
  IN2 w0.117: v1(16.05,87.64) 16.23,87.46 16.23,86.92 16.85,86.29 16.85,86.01 v1(16.6,85.76)
  BOTTOM w0.131: v1(16.05,87.64) 16.17,87.76 16.17,88.02 15.75,88.43 J1HDMI1.12 ; v1(16.6,85.76) 16.85,86.01 16.85,86.24 17.12,86.5 17.89,86.5 18.07,86.33 19.18,86.33 19.34,86.49 L1HDMI1.2
DDI0_HDMI_CLK_DN_CH: length 7.4
  TOP w0.131: EU1HDMI1.18 25.19,87.81 25.12,87.74 24.75,87.74 24.62,87.61 23.68,87.61 23.38,87.3 23.38,86.61 23.24,86.48 23.03,86.48 v1(22.78,86.73) 22.51,86.46 22.03,86.46 R1HDMI10.1
  BOTTOM w0.131: L1HDMI1.1 21.47,86.49 21.62,86.33 21.93,86.33 22.07,86.47 22.52,86.47 v1(22.78,86.73)
DDI0_HDMI_CLK_DP: length 2.7
  TOP w0.131: EU1HDMI1.9 29.24,87.41 29.32,87.5 29.6,87.5 29.87,87.76 29.87,88.13 30.15,88.41 30.3,88.41 30.42,88.29 C1HDMI1.1
DDI0_HDMI_CLK_DP_ALS: length 13.3
  TOP w0.131: R1HDMI9.2 20.49,86.2 19.25,86.2 19.09,86.35 17.29,86.35 17.08,86.14 17.08,86.01 v1(17.34,85.76)
  IN2 w0.117: v1(17.34,85.76) 17.07,86.02 17.07,86.39 16.45,87.01 16.45,87.46 v1(16.62,87.64)
  BOTTOM w0.131: L1HDMI1.3 19.16,85.94 19,86.1 17.97,86.1 17.79,86.27 17.21,86.27 17.08,86.14 17.08,86.01 v1(17.34,85.76) ; J1HDMI1.10 16.75,88.37 16.4,88.02 16.4,87.85 16.61,87.64 v1(16.62,87.64)
DDI0_HDMI_CLK_DP_CH: length 7.4
  TOP w0.131: R1HDMI9.1 22.03,86.22 22.55,86.22 v1(22.78,85.99) 23.03,86.24 23.34,86.24 23.61,86.51 23.61,87.21 23.78,87.38 24.72,87.38 24.85,87.51 25.09,87.51 25.19,87.41 EU1HDMI1.19
  BOTTOM w0.131: L1HDMI1.4 21.47,85.94 21.62,86.1 22.03,86.1 22.17,86.24 22.54,86.24 v1(22.78,85.99)
DDI0_HDMI_D0_DN: length 2
  TOP w0.131: C1HDMI4.1 30.41,86.64 30.21,86.45 29.81,86.45 29.76,86.5 29.35,86.5 29.24,86.61 EU1HDMI1.7
DDI0_HDMI_D0_DN_ALS: length 14.3
  TOP w0.131: v1(24.06,86.94) 24.06,86.93 24.19,86.81 24.62,86.81 24.91,86.52 25.1,86.52 25.15,86.58 25.16,86.58 25.19,86.61 EU1HDMI1.21 ; J1HDMI1.9 17.25,88.57 17.71,88.11 17.71,87.91 17.71,87.91 17.71,87.81 v1(17.54,87.64)
  IN2 w0.117: v1(17.54,87.64) 17.74,87.84 17.74,88.21 19.18,89.64 21.69,89.64 22.46,88.87 22.46,87.92 23.58,86.81 23.93,86.81 v1(24.06,86.94)
DDI0_HDMI_D0_DP: length 2
  TOP w0.131: C1HDMI3.1 30.41,86.05 30.23,86.22 29.71,86.22 29.66,86.27 29.3,86.27 29.24,86.21 EU1HDMI1.6
DDI0_HDMI_D0_DP_ALS: length 14.2
  TOP w0.131: EU1HDMI1.22 25.19,86.21 25.11,86.29 24.81,86.29 24.53,86.58 24.24,86.58 24.06,86.4 v1(24.06,86.26) ; v1(18.12,87.64) 17.95,87.81 17.95,88.1 18.25,88.4 J1HDMI1.7
  IN2 w0.117: v1(18.12,87.64) 17.96,87.79 17.96,88.12 19.27,89.42 21.6,89.42 22.24,88.78 22.24,87.83 23.48,86.59 23.93,86.59 24.06,86.45 v1(24.06,86.26)
DDI0_HDMI_D1_DN: length 3.6
  TOP w0.131: EU1HDMI1.5 29.73,85.81 30.13,85.41 31.04,85.41 31.04,85.41 31.23,85.41 31.48,85.16 31.48,85.02 C1HDMI6.1
DDI0_HDMI_D1_DN_ALS: length 15
  TOP w0.131: EU1HDMI1.23 25.26,85.81 25.09,85.64 24.91,85.64 24.7,85.44 24.24,85.44 v1(24.06,85.61)
  IN2 w0.117: v1(19.05,87.64) 19.18,87.77 19.24,87.83 19.24,88.64 19.53,88.93 20.2,88.93 20.42,88.7 20.66,88.7 20.89,88.93 21.39,88.93 21.75,88.57 21.75,87.6 22.14,87.21 22.14,86.87 21.59,86.33 21.59,86.18 21.91,85.87 22.26,85.87 22.54,85.59 22.54,85.24 22.68,85.1 23.13,85.1 23.52,85.49 23.94,85.49 v1(24.06,85.61)
  BOTTOM w0.131: J1HDMI1.6 18.75,88.72 19.15,88.33 19.15,87.74 v1(19.05,87.64)
DDI0_HDMI_D1_DP: length 3.6
  TOP w0.131: EU1HDMI1.4 29.16,85.41 29.32,85.58 29.64,85.58 30.04,85.18 31.13,85.18 31.25,85.06 31.25,84.82 31.13,84.7 C1HDMI5.1
DDI0_HDMI_D1_DP_ALS: length 14.9
  TOP w0.131: EU1HDMI1.24 25,85.41 24.8,85.2 24.24,85.2 24.06,85.03 v1(24.06,84.93)
  IN2 w0.117: v1(19.62,87.64) 19.46,87.8 19.46,88.55 19.62,88.71 20.1,88.71 20.33,88.48 20.75,88.48 20.98,88.71 21.3,88.71 21.53,88.48 21.53,87.51 21.92,87.12 21.92,86.96 21.37,86.42 21.37,86.09 21.82,85.65 22.17,85.65 22.32,85.5 22.32,85.15 22.59,84.88 23.22,84.88 23.61,85.27 23.88,85.27 24.06,85.08 v1(24.06,84.93)
  BOTTOM w0.131: J1HDMI1.4 19.75,88.68 19.38,88.31 19.38,87.88 v1(19.62,87.64)
DDI0_HDMI_D2_DN: length 3.5
  TOP w0.131: EU1HDMI1.2 29.56,84.61 29.8,84.37 29.8,83.96 29.42,83.58 v1(29.42,83.44)
  BOTTOM w0.131: C1HDMI8.1 29.36,82.73 29.36,83.38 v1(29.42,83.44)
DDI0_HDMI_D2_DN_ALS: length 16.3
  TOP w0.131: J1HDMI1.3 20.25,88.83 20.63,88.45 20.63,87.85 v1(20.42,87.64) ; v1(23.75,83.11) 23.97,83.32 23.97,83.73 24.48,84.24 24.7,84.24 24.9,84.44 25.11,84.44 25.27,84.61 EU1HDMI1.26
  IN2 w0.117: v1(23.75,83.11) 23.91,83.27 23.91,83.99 23.74,84.17 22.29,84.17 20.84,85.61 18.91,85.61 18.68,85.84 18.68,86.65 18.94,86.91 20.41,86.91 20.56,87.06 20.56,87.51 v1(20.42,87.64)
DDI0_HDMI_D2_DP: length 3.4
  TOP w0.131: EU1HDMI1.1 29.1,84.21 29.27,84.38 29.46,84.38 29.57,84.27 29.57,84.05 29.33,83.81 29.27,83.81 28.9,83.44 v1(28.9,83.44)
  BOTTOM w0.131: v1(28.9,83.44) 29.13,83.21 29.13,82.88 C1HDMI7.1
DDI0_HDMI_D2_DP_ALS: length 16.2
  TOP w0.131: v1(21,87.64) 20.87,87.77 20.87,88.27 21.25,88.66 J1HDMI1.1 ; EU1HDMI1.27 25,84.21 24.8,84.01 24.58,84.01 24.2,83.63 24.2,83.22 24.31,83.11 v1(24.47,83.11)
  IN2 w0.117: v1(24.47,83.11) 24.36,83.11 24.13,83.34 24.13,84.08 23.83,84.38 22.38,84.38 20.93,85.83 19,85.83 18.9,85.93 18.9,86.56 19.03,86.69 20.5,86.69 20.78,86.97 20.78,87.42 v1(21,87.64)
DDI0_HDMI_HPD_ALS: length 19.8
  TOP w0.102: EU1HDMI1.25 25.15,85.01 v1(25,84.87) ; v1(14.16,87.33) 12.33,87.33 11.85,87.81 11.85,88.55 12.25,88.95 J1HDMI1.19
  BOTTOM w0.102: v1(14.16,87.33) 15.53,87.33 15.8,87.06 15.8,85.89 16.49,85.2 17.62,85.2 17.93,85.5 22.96,85.5 24.23,84.23 24.79,84.23 25,84.45 v1(25,84.87)
DDI0_HDMI_HPD_ESD: length 5.6
  TOP w0.102: EU1HDMI1.3 29.68,85.01 29.88,84.81 29.95,84.81 v1(30.07,84.69)
  BOTTOM w0.102: Q1HDMI2.1 30.44,85.06 v1(30.07,84.69) 30.07,84.5 29.61,84.04 27.82,84.04 R1HDMI6.2
DDI0_HDMI_SCL: length 67
  TOP w0.102: U1.C13 6.92,52.48 6.56,52.84
  TOP w0.131: 6.56,52.84 5.47,52.84 5.32,52.99 4.16,52.99 R1HDMI4.1 3.96,52.58 v1(4.79,52.58) ; v1(24.93,82.53) 24.93,82.33 25.09,82.17 25.51,82.17 25.99,81.7 27.6,81.7 27.78,81.88 27.78,82.52 27.61,82.69 EU1HDMI1.31
  IN1 w0.102: 4.48,52.95 4.79,52.64 v1(4.79,52.58)
  IN1 w0.117: v1(24.93,82.53) 24.69,82.53 24.57,82.66 23.62,82.66 23.18,83.09 23.18,83.46 20.87,85.78 19.62,85.78 18.53,86.87 7.84,86.87 1.42,80.44 1.42,73.18 1.47,73.13 1.47,70.19 1.33,70.06 1.33,56.92 2.47,55.79 2.97,55.28 3.9,54.36 3.9,53.38 4.15,53.13 4.31,53.13 4.48,52.95
DDI0_HDMI_SCL_ALS: length 34.7
  TOP w0.381: J1HDMI1.15 14.25,88.13 v1(14.34,88.04)
  IN1 w0.381: v1(26.17,82.22) 26.17,83.05 25.6,83.62 23.74,83.62 23.68,83.69 23.67,83.69 21.47,85.88 21.47,88.73 21.13,89.07 21.05,89.07 15.37,89.07 v1(14.34,88.04)
  IN2 w0.381: v1(26.17,82.22) 26.17,81.9 26.44,81.63 26.55,81.53 26.72,81.53 28.8,79.44 28.8,71.67 v1(30.49,69.98)
  BOTTOM w0.381: R57.1 30.29,70.39 v1(30.49,69.98)
DDI0_HDMI_SDA: length 67.6
  TOP w0.102: U1.D13 7.52,52.76 7.47,52.81 7.05,52.81 6.78,53.09 6.78,53.27 6.68,53.37
  TOP w0.131: v1(4.69,53.95) 4.1,53.95 R1HDMI5.1 4.05,53.51 6.54,53.51 6.68,53.37 ; EU1HDMI1.32 28.01,81.78 27.7,81.46 25.89,81.46 25.41,81.94 24.99,81.94 24.66,82.28 v1(24.47,82.28)
  IN1 w0.102: 4.48,53.34 4.69,53.55 v1(4.69,53.95)
  IN1 w0.117: 4.48,53.34 4.46,53.32 4.23,53.32 4.09,53.46 4.09,54.44 3.11,55.42 2.61,55.92 2.55,55.98 1.53,57 1.53,69.98 1.66,70.11 1.66,73.21 1.61,73.26 1.61,80.36 7.92,86.67 18.45,86.67 19.54,85.59 20.79,85.59 22.99,83.38 22.99,83.01 23.54,82.46 24.3,82.46 24.47,82.29 v1(24.47,82.28)
